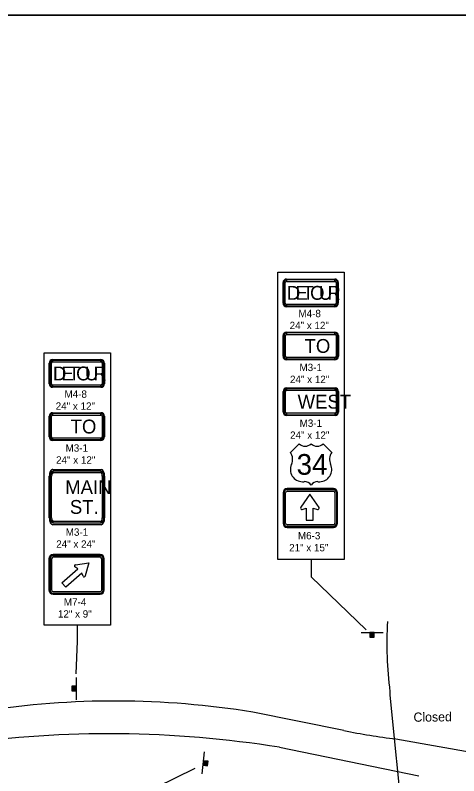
# Model space of a CAD drawing. Extents: x 10133 to 81668, y 6132 to 11018.
# Drawn here: x 11517 to 11999, y 9117 to 9944 of the extents above; entities that cross this region are included whole.
import ezdxf

# ---------------------------------------------------------------- set-up
doc = ezdxf.new("R2010")
doc.units = 0
for name, color, linetype in [('dsnTextFinalPlan', 7, 'Continuous'), ('Level 10', 7, 'Continuous'), ('Level 2', 7, 'Continuous'), ('Level 4', 7, 'Continuous'), ('Level 5', 7, 'Continuous'), ('SheetBorder', 7, 'Continuous'), ('SheetText', 7, 'Continuous')]:
    doc.layers.add(name, color=color, linetype=linetype)

msp = doc.modelspace()

# ---------------------------------------------------------------- linework, layer by layer
at = {"layer": 'dsnTextFinalPlan'}
for p, q in [((11554, 9353.14), (11554, 9319.35)), ((11609.55, 9357.72), (11558.58, 9357.72)), ((11614.13, 9319.35), (11614.13, 9353.14)), ((11558.58, 9314.77), (11609.55, 9314.77)), ((11893.21, 9273.15), (11917.21, 9273.15)), ((11907.57, 9272.79), (11902.69, 9272.79)), ((11902.69, 9272.54), (11907.57, 9272.54)), ((11907.57, 9272.31), (11902.69, 9272.31)), ((11902.69, 9272.08), (11907.57, 9272.08)), ((11907.57, 9271.89), (11902.69, 9271.89)), ((11902.69, 9271.71), (11907.57, 9271.71)), ((11907.57, 9271.41), (11902.69, 9271.41)), ((11902.69, 9271.18), (11907.57, 9271.18)), ((11907.57, 9270.99), (11902.69, 9271)), ((11902.69, 9270.71), (11907.57, 9270.71)), ((11907.57, 9270.38), (11902.69, 9270.38)), ((11902.69, 9270), (11907.57, 9270)), ((11907.57, 9269.81), (11902.69, 9269.82)), ((11902.69, 9269.45), (11907.57, 9269.43)), ((11907.57, 9269.25), (11902.69, 9269.25)), ((11902.69, 9268.97), (11907.57, 9268.97)), ((11907.57, 9268.78), (11902.69, 9268.78)), ((11902.69, 9268.5), (11907.57, 9268.5)), ((11583.66, 9224.07), (11583.66, 9200.07)), ((11579.01, 9214.59), (11579.01, 9209.71)), ((11579.29, 9209.71), (11579.29, 9214.59)), ((11579.49, 9214.59), (11579.49, 9209.71)), ((11579.77, 9209.71), (11579.77, 9214.59)), ((11579.96, 9214.59), (11579.95, 9209.71)), ((11580.32, 9209.71), (11580.34, 9214.59)), ((11580.52, 9214.59), (11580.52, 9209.71)), ((11580.89, 9209.71), (11580.89, 9214.59)), ((11581.22, 9214.59), (11581.22, 9209.71)), ((11581.5, 9209.71), (11581.52, 9214.59)), ((11581.7, 9214.59), (11581.7, 9209.71)), ((11581.93, 9209.71), (11581.93, 9214.59)), ((11582.22, 9214.59), (11582.22, 9209.71)), ((11582.4, 9209.71), (11582.4, 9214.59)), ((11582.6, 9214.59), (11582.6, 9209.71)), ((11582.83, 9209.71), (11582.83, 9214.59)), ((11583.05, 9214.59), (11583.05, 9209.71)), ((11583.3, 9209.71), (11583.3, 9214.59)), ((11874.53, 9166.61), (11775.63, 9186.42)), ((11931.03, 9157.44), (12148.4, 9119.44)), ((11720.39, 9119.35), (11723.1, 9143.2)), ((11804.44, 9148.37), (11956.07, 9117.16)), ((11722.37, 9133.58), (11721.82, 9128.73)), ((11722.06, 9128.7), (11722.61, 9133.55)), ((11722.84, 9133.52), (11722.29, 9128.68)), ((11722.52, 9128.65), (11723.07, 9133.5)), ((11723.27, 9133.47), (11722.71, 9128.63)), ((11722.89, 9128.61), (11723.44, 9133.45)), ((11723.74, 9133.42), (11723.19, 9128.57)), ((11723.41, 9128.55), (11723.96, 9133.39)), ((11724.16, 9133.37), (11723.59, 9128.53)), ((11723.89, 9128.5), (11724.44, 9133.34)), ((11724.76, 9133.3), (11724.21, 9128.46)), ((11724.58, 9128.42), (11725.13, 9133.26)), ((11725.33, 9133.24), (11724.76, 9128.4)), ((11725.14, 9128.35), (11725.7, 9133.2)), ((11725.88, 9133.18), (11725.33, 9128.33)), ((11725.61, 9128.3), (11726.16, 9133.15)), ((11726.35, 9133.12), (11725.8, 9128.28)), ((11726.08, 9128.25), (11726.63, 9133.09))]:
    msp.add_line(p, q, dxfattribs=at)
for points in [[(11802.9, 9664.76), (11874.97, 9664.76), (11874.97, 9352.54), (11802.9, 9352.54)], [(11802.9, 9664.76), (11874.97, 9664.76), (11874.97, 9352.54), (11802.9, 9352.54)], [(11548.64, 9577.16), (11620.7, 9577.16), (11620.7, 9281.07), (11548.64, 9281.07)], [(11548.64, 9577.16), (11620.7, 9577.16), (11620.7, 9281.07), (11548.64, 9281.07)], [(11907.57, 9273.06), (11902.66, 9273.06), (11902.66, 9268.15), (11907.57, 9268.15)], [(11583.58, 9209.71), (11583.58, 9214.62), (11578.67, 9214.62), (11578.67, 9209.71)], [(11722.09, 9133.61), (11721.54, 9128.73), (11726.42, 9128.17), (11726.97, 9133.05)]]:
    msp.add_lwpolyline(points, close=True, dxfattribs=at)
for points in [[(11838.93, 9352.54), (11838.93, 9333.57), (11898.89, 9275.89)], [(11591.14, 9334.16), (11589.52, 9337.67), (11572.19, 9322.38), (11568.03, 9327.09), (11585.36, 9342.38), (11582.06, 9344.41)], [(11582.85, 9346.58), (11597.21, 9348.65), (11593.35, 9334.67)], [(11584.67, 9281.07), (11584.67, 9263.58), (11583.34, 9228.28)], [(11924.53, 9208.75), (11924.53, 9205.04), (11938.44, 9064.44), (11960.57, 8858.09), (11970.22, 8724.25)], [(11587.6, 9045.25), (11587.6, 9064.06), (11712.82, 9125.45)]]:
    msp.add_lwpolyline(points, dxfattribs=at)
for centre, radius, start, end in [((11558.58, 9353.14), 4.58, 90, 180), ((11609.55, 9353.14), 4.58, 360, 90), ((11582.69, 9345.39), 1.16, 98.0346, 237.39274), ((11566.32, 9461.36), 115.96, 278.0346, 278.19506), ((11592.17, 9334.65), 1.14, 205.45459, 344.73406), ((11705.14, 9303.81), 115.96, 164.56669, 164.73406), ((11558.58, 9319.35), 4.58, 180, 270), ((11609.55, 9319.35), 4.58, 270, 0), ((12350.91, 9261.93), 429.68, 176.925, 187.10976), ((11625.49, 8265.99), 932.6, 80.73564, 98.86822), ((11618.87, 7976.32), 1186.65, 81.00318, 97.8988), ((12002.83, 9778.7), 625.39, 258.1619, 263.40729)]:
    msp.add_arc(centre, radius, start, end, dxfattribs=at)
at = {"layer": 'Level 10'}
for p, q in [((11812.11, 9657.25), (11864.72, 9657.25)), ((11812.11, 9654.75), (11812.11, 9656.31)), ((11864.72, 9656.31), (11864.72, 9654.75)), ((11808.35, 9630.95), (11808.35, 9653.49)), ((11809.29, 9653.49), (11810.85, 9653.49)), ((11865.97, 9653.49), (11867.54, 9653.49)), ((11868.48, 9653.49), (11868.48, 9630.95)), ((11810.85, 9630.95), (11809.29, 9630.95)), ((11867.54, 9630.95), (11865.97, 9630.95)), ((11812.11, 9628.13), (11812.11, 9629.69)), ((11864.72, 9627.19), (11812.11, 9627.19)), ((11864.72, 9629.69), (11864.72, 9628.13)), ((11812.15, 9599.57), (11864.77, 9599.57)), ((11812.15, 9597.06), (11812.15, 9598.63)), ((11864.77, 9598.63), (11864.77, 9597.06)), ((11808.4, 9573.26), (11808.4, 9595.81)), ((11809.34, 9595.81), (11810.9, 9595.81)), ((11866.02, 9595.81), (11867.58, 9595.81)), ((11868.52, 9595.81), (11868.52, 9573.26)), ((11810.9, 9573.26), (11809.34, 9573.26)), ((11867.58, 9573.26), (11866.02, 9573.26)), ((11554.09, 9543.35), (11554.09, 9565.89)), ((11555.02, 9565.89), (11556.59, 9565.89)), ((11557.84, 9569.65), (11610.46, 9569.65)), ((11557.84, 9567.15), (11557.84, 9568.71)), ((11610.46, 9568.71), (11610.46, 9567.15)), ((11611.71, 9565.89), (11613.27, 9565.89)), ((11614.21, 9565.89), (11614.21, 9543.35)), ((11812.15, 9570.44), (11812.15, 9572.01)), ((11864.77, 9569.5), (11812.15, 9569.5)), ((11864.77, 9572.01), (11864.77, 9570.44)), ((11556.59, 9543.35), (11555.02, 9543.35)), ((11557.84, 9540.53), (11557.84, 9542.09)), ((11610.46, 9542.09), (11610.46, 9540.53)), ((11613.27, 9543.35), (11611.71, 9543.35)), ((11610.46, 9539.59), (11557.84, 9539.59)), ((11808.51, 9512.64), (11808.51, 9535.19)), ((11809.45, 9535.19), (11811.02, 9535.19)), ((11812.27, 9538.95), (11864.88, 9538.95)), ((11812.27, 9536.44), (11812.27, 9538.01)), ((11864.88, 9538.01), (11864.88, 9536.44)), ((11866.14, 9535.19), (11867.7, 9535.19)), ((11868.64, 9535.19), (11868.64, 9512.64)), ((11554.13, 9485.66), (11554.13, 9508.21)), ((11555.07, 9508.21), (11556.64, 9508.21)), ((11557.89, 9511.97), (11610.5, 9511.97)), ((11557.89, 9509.46), (11557.89, 9511.03)), ((11610.5, 9511.03), (11610.5, 9509.46)), ((11611.75, 9508.21), (11613.32, 9508.21)), ((11614.26, 9508.21), (11614.26, 9485.66)), ((11811.02, 9512.64), (11809.45, 9512.64)), ((11812.27, 9509.82), (11812.27, 9511.39)), ((11864.88, 9508.88), (11812.27, 9508.88)), ((11864.88, 9511.39), (11864.88, 9509.82)), ((11867.7, 9512.64), (11866.14, 9512.64)), ((11556.64, 9485.66), (11555.07, 9485.66)), ((11557.89, 9482.84), (11557.89, 9484.41)), ((11610.5, 9484.41), (11610.5, 9482.84)), ((11613.32, 9485.66), (11611.75, 9485.66)), ((11610.5, 9481.9), (11557.89, 9481.9)), ((11558.08, 9450.38), (11610.69, 9450.38)), ((11554.32, 9397.77), (11554.32, 9442.87)), ((11555.26, 9442.87), (11556.83, 9442.87)), ((11558.08, 9445.37), (11558.08, 9448.5)), ((11610.69, 9448.5), (11610.69, 9446.94)), ((11611.95, 9442.87), (11613.51, 9442.87)), ((11614.45, 9442.87), (11614.45, 9397.77)), ((11808.39, 9425.04), (11808.39, 9391.78)), ((11809.52, 9391.78), (11809.52, 9425.04)), ((11811.22, 9391.78), (11811.22, 9425.04)), ((11863.06, 9429.55), (11812.89, 9429.55)), ((11812.91, 9428.42), (11863.08, 9428.42)), ((11812.91, 9426.73), (11863.08, 9426.73)), ((11864.77, 9425.04), (11864.77, 9391.78)), ((11866.46, 9425.04), (11866.46, 9391.78)), ((11867.57, 9391.78), (11867.57, 9425.04)), ((11837.47, 9423.46), (11827.55, 9409.2)), ((11847.56, 9409.02), (11837.47, 9423.46)), ((11829.29, 9406.93), (11833.64, 9408.33)), ((11833.64, 9408.33), (11833.64, 9395.28)), ((11841.3, 9408.15), (11841.3, 9408.33)), ((11841.3, 9408.33), (11845.82, 9406.93)), ((11841.3, 9395.1), (11841.3, 9408.15)), ((11556.83, 9397.77), (11555.26, 9397.77)), ((11558.08, 9392.13), (11558.08, 9395.27)), ((11610.69, 9393.7), (11610.69, 9392.13)), ((11613.51, 9397.77), (11611.95, 9397.77)), ((11833.64, 9395.28), (11833.64, 9395.1)), ((11833.64, 9395.1), (11841.3, 9395.1)), ((11610.69, 9390.25), (11558.08, 9390.25)), ((11812.89, 9387.27), (11863.06, 9387.27)), ((11863.08, 9390.09), (11812.91, 9390.09)), ((11863.08, 9388.4), (11812.91, 9388.4)), ((11555.15, 9353.14), (11555.15, 9319.35)), ((11556.87, 9353.14), (11556.87, 9319.35)), ((11609.55, 9356.57), (11558.58, 9356.57)), ((11609.55, 9354.86), (11558.58, 9354.86)), ((11611.27, 9319.35), (11611.27, 9353.14)), ((11612.99, 9319.35), (11612.99, 9353.14)), ((11558.58, 9317.63), (11609.55, 9317.63)), ((11558.58, 9315.92), (11609.55, 9315.92))]:
    msp.add_line(p, q, dxfattribs=at)
for points in [[(11864.72, 9656.31), (11812.11, 9656.31), (11812.11, 9654.75), (11864.72, 9654.75), (11864.72, 9656.31)], [(11809.29, 9653.49), (11809.29, 9630.95), (11810.85, 9630.95), (11810.85, 9653.49), (11809.29, 9653.49)], [(11867.54, 9630.95), (11867.54, 9653.49), (11865.97, 9653.49), (11865.97, 9630.95), (11867.54, 9630.95)], [(11812.11, 9628.13), (11864.72, 9628.13), (11864.72, 9629.69), (11812.11, 9629.69), (11812.11, 9628.13)], [(11864.77, 9598.63), (11812.15, 9598.63), (11812.15, 9597.06), (11864.77, 9597.06), (11864.77, 9598.63)], [(11809.34, 9595.81), (11809.34, 9573.26), (11810.9, 9573.26), (11810.9, 9595.81), (11809.34, 9595.81)], [(11867.58, 9573.26), (11867.58, 9595.81), (11866.02, 9595.81), (11866.02, 9573.26), (11867.58, 9573.26)], [(11555.02, 9565.89), (11555.02, 9543.35), (11556.59, 9543.35), (11556.59, 9565.89), (11555.02, 9565.89)], [(11610.46, 9568.71), (11557.84, 9568.71), (11557.84, 9567.15), (11610.46, 9567.15), (11610.46, 9568.71)], [(11613.27, 9543.35), (11613.27, 9565.89), (11611.71, 9565.89), (11611.71, 9543.35), (11613.27, 9543.35)], [(11812.15, 9570.44), (11864.77, 9570.44), (11864.77, 9572.01), (11812.15, 9572.01), (11812.15, 9570.44)], [(11557.84, 9540.53), (11610.46, 9540.53), (11610.46, 9542.09), (11557.84, 9542.09), (11557.84, 9540.53)], [(11809.45, 9535.19), (11809.45, 9512.64), (11811.02, 9512.64), (11811.02, 9535.19), (11809.45, 9535.19)], [(11864.88, 9538.01), (11812.27, 9538.01), (11812.27, 9536.44), (11864.88, 9536.44), (11864.88, 9538.01)], [(11867.7, 9512.64), (11867.7, 9535.19), (11866.14, 9535.19), (11866.14, 9512.64), (11867.7, 9512.64)], [(11555.07, 9508.21), (11555.07, 9485.66), (11556.64, 9485.66), (11556.64, 9508.21), (11555.07, 9508.21)], [(11610.5, 9511.03), (11557.89, 9511.03), (11557.89, 9509.46), (11610.5, 9509.46), (11610.5, 9511.03)], [(11613.32, 9485.66), (11613.32, 9508.21), (11611.75, 9508.21), (11611.75, 9485.66), (11613.32, 9485.66)], [(11812.27, 9509.82), (11864.88, 9509.82), (11864.88, 9511.39), (11812.27, 9511.39), (11812.27, 9509.82)], [(11557.89, 9482.84), (11610.5, 9482.84), (11610.5, 9484.41), (11557.89, 9484.41), (11557.89, 9482.84)], [(11555.26, 9442.87), (11555.26, 9397.77), (11556.83, 9397.77), (11556.83, 9442.87), (11555.26, 9442.87)], [(11610.69, 9448.5), (11558.08, 9448.5), (11558.08, 9446.94), (11610.69, 9446.94), (11610.69, 9448.5)], [(11613.51, 9397.77), (11613.51, 9442.87), (11611.95, 9442.87), (11611.95, 9397.77), (11613.51, 9397.77)], [(11558.08, 9392.13), (11610.69, 9392.13), (11610.69, 9393.7), (11558.08, 9393.7), (11558.08, 9392.13)]]:
    msp.add_lwpolyline(points, close=True, dxfattribs=at)
for centre, radius, start, end in [((11812.11, 9653.49), 3.76, 90, 180), ((11812.11, 9653.49), 2.82, 90.00021, 179.99985), ((11864.72, 9653.49), 3.76, 0, 90), ((11864.72, 9653.49), 2.82, 0, 90.00021), ((11812.11, 9653.49), 1.25, 90.00021, 179.99985), ((11864.72, 9653.49), 1.25, 0, 90.00021), ((11812.11, 9630.95), 3.76, 180, 270), ((11812.11, 9630.95), 2.82, 179.99985, 270.00006), ((11812.11, 9630.95), 1.25, 179.99985, 270.00006), ((11864.72, 9630.95), 2.82, 270.00006, 0.00027), ((11864.72, 9630.95), 1.25, 270.00006, 0.00027), ((11864.72, 9630.95), 3.76, 270, 359.99112), ((11812.15, 9595.81), 3.76, 90, 180), ((11812.15, 9595.81), 2.82, 90.00021, 179.99985), ((11864.77, 9595.81), 3.76, 0, 90), ((11864.77, 9595.81), 2.82, 0, 90.00021), ((11812.15, 9595.81), 1.25, 90.00021, 179.99985), ((11864.77, 9595.81), 1.25, 0, 90.00021), ((11812.15, 9573.26), 3.76, 180, 270), ((11812.15, 9573.26), 2.82, 179.99985, 270.00006), ((11812.15, 9573.26), 1.25, 179.99985, 270.00006), ((11864.77, 9573.26), 2.82, 270.00006, 0.00027), ((11864.77, 9573.26), 1.25, 270.00006, 0.00027), ((11864.77, 9573.26), 3.76, 270, 359.99112), ((11557.84, 9565.89), 3.76, 90, 180), ((11557.84, 9565.89), 2.82, 90.00021, 179.99985), ((11557.84, 9565.89), 1.25, 90.00021, 179.99985), ((11610.46, 9565.89), 3.76, 0, 90), ((11610.46, 9565.89), 2.82, 0, 90.00021), ((11610.46, 9565.89), 1.25, 0, 90.00021), ((11557.84, 9543.35), 3.76, 180, 270), ((11557.84, 9543.35), 2.82, 179.99985, 270.00006), ((11557.84, 9543.35), 1.25, 179.99985, 270.00006), ((11610.46, 9543.35), 2.82, 270.00006, 0.00027), ((11610.46, 9543.35), 1.25, 270.00006, 0.00027), ((11610.46, 9543.35), 3.76, 270, 359.99112), ((11812.27, 9535.19), 3.76, 90, 180), ((11812.27, 9535.19), 2.82, 90.00021, 179.99985), ((11812.27, 9535.19), 1.25, 90.00021, 179.99985), ((11864.88, 9535.19), 3.76, 0, 90), ((11864.88, 9535.19), 2.82, 0, 90.00021), ((11864.88, 9535.19), 1.25, 0, 90.00021), ((11557.89, 9508.21), 3.76, 90, 180), ((11557.89, 9508.21), 2.82, 90.00021, 179.99985), ((11557.89, 9508.21), 1.25, 90.00021, 179.99985), ((11610.5, 9508.21), 3.76, 0, 90), ((11610.5, 9508.21), 2.82, 0, 90.00021), ((11610.5, 9508.21), 1.25, 0, 90.00021), ((11812.27, 9512.64), 3.76, 180, 270), ((11812.27, 9512.64), 2.82, 179.99985, 270.00006), ((11812.27, 9512.64), 1.25, 179.99985, 270.00006), ((11864.88, 9512.64), 2.82, 270.00006, 0.00027), ((11864.88, 9512.64), 1.25, 270.00006, 0.00027), ((11864.88, 9512.64), 3.76, 270, 359.99112), ((11557.89, 9485.66), 3.76, 180, 270), ((11557.89, 9485.66), 2.82, 179.99985, 270.00006), ((11557.89, 9485.66), 1.25, 179.99985, 270.00006), ((11610.5, 9485.66), 2.82, 270.00006, 0.00027), ((11610.5, 9485.66), 1.25, 270.00006, 0.00027), ((11610.5, 9485.66), 3.76, 270, 359.99112), ((11812.89, 9425.04), 4.51, 90, 180), ((11812.91, 9425.04), 3.38, 90, 180), ((11812.91, 9425.04), 1.69, 90, 180), ((11863.06, 9425.04), 4.51, 360, 90), ((11863.08, 9425.04), 3.38, 0, 90), ((11863.08, 9425.04), 1.69, 0, 90), ((11828.76, 9408.33), 1.49, 144.26784, 290.86935), ((11846.21, 9408.38), 1.5, 254.96957, 25.41929), ((11812.89, 9391.78), 4.51, 180, 270), ((11812.91, 9391.78), 3.38, 180, 270), ((11812.91, 9391.78), 1.69, 180, 270), ((11863.06, 9391.78), 4.51, 270, 0), ((11863.08, 9391.78), 3.38, 270, 0), ((11863.08, 9391.78), 1.69, 270, 0), ((11558.58, 9353.14), 3.44, 90, 180), ((11558.58, 9353.14), 1.72, 90, 180), ((11609.55, 9353.14), 3.44, 0, 90), ((11609.55, 9353.14), 1.72, 0, 90), ((11558.58, 9319.35), 3.44, 180, 270), ((11558.58, 9319.35), 1.72, 180, 270), ((11609.55, 9319.35), 3.44, 270, 360), ((11609.55, 9319.35), 1.72, 270, 0)]:
    msp.add_arc(centre, radius, start, end, dxfattribs=at)
for centre, major_axis, ratio, start_param, end_param in [((11558.08, 9442.87), (0, 7.52), 0.5, 6.283185, 7.853982), ((11610.69, 9442.87), (0, 7.52), 0.5, 4.712389, 6.283185), ((11558.08, 9442.87), (0, 5.64), 0.5, 0.000004, 1.570794), ((11558.08, 9442.87), (0, 4.07), 0.307692, 0.000004, 1.570794), ((11610.69, 9442.87), (0, 5.64), 0.5, 4.712389, 6.283189), ((11610.69, 9442.87), (0, 4.07), 0.307692, 4.712389, 6.283189), ((11558.08, 9397.77), (0, 7.52), 0.5, 1.570796, 3.141593), ((11558.08, 9397.77), (0, 5.64), 0.5, 1.570794, 3.141594), ((11558.08, 9397.77), (0, 4.07), 0.307692, 1.570794, 3.141594), ((11610.69, 9397.77), (0, 5.64), 0.5, 3.141594, 4.712394), ((11610.69, 9397.77), (0, 4.07), 0.307692, 3.141594, 4.712394), ((11610.69, 9397.77), (0, 7.52), 0.5, 3.141593, 4.712234)]:
    msp.add_ellipse(centre, major_axis=major_axis, ratio=ratio, start_param=start_param, end_param=end_param, dxfattribs=at)
at = {"layer": 'Level 4'}
for p, q in [((11825.75, 9478.27), (11816.38, 9468.9)), ((11825.75, 9478.27), (11816.38, 9468.9)), ((11861.38, 9468.9), (11852, 9478.27)), ((11861.38, 9468.9), (11852, 9478.27)), ((11829.5, 9437.02), (11831.38, 9437.02)), ((11829.5, 9437.02), (11831.38, 9437.02)), ((11846.38, 9437.02), (11848.25, 9437.02)), ((11846.38, 9437.02), (11848.25, 9437.02))]:
    msp.add_line(p, q, dxfattribs=at)
for centre, radius, start, end in [((11832.31, 9484.97), 9.38, 225.57291, 314.42721), ((11832.31, 9484.97), 9.38, 225.57291, 314.42721), ((11845.44, 9484.97), 9.38, 225.57291, 314.42721), ((11845.44, 9484.97), 9.38, 225.57291, 314.42721), ((11805.71, 9461.25), 13.13, 334.98952, 35.66288), ((11805.71, 9461.25), 13.13, 334.98952, 35.66288), ((11872.04, 9461.25), 13.13, 144.33724, 205.01003), ((11872.04, 9461.25), 13.13, 144.33724, 205.01003), ((11829.5, 9450.15), 13.13, 154.98967, 270.00006), ((11829.5, 9450.15), 13.13, 154.98967, 270.00006), ((11848.25, 9450.15), 13.13, 270.00006, 25.01045), ((11848.25, 9450.15), 13.13, 270.00006, 25.01045), ((11831.38, 9427.65), 9.38, 36.86989, 90.00021), ((11831.38, 9427.65), 9.38, 36.86989, 90.00021), ((11846.38, 9427.65), 9.38, 90.00021, 143.13001), ((11846.38, 9427.65), 9.38, 90.00021, 143.13001)]:
    msp.add_arc(centre, radius, start, end, dxfattribs=at)
at = {"layer": 'SheetBorder'}
msp.add_lwpolyline([(10132.52, 9944.02), (13267.53, 9944.02), (13267.53, 7924.02), (10132.52, 7924.02)], close=True, dxfattribs=at)
at = {"layer": 'SheetText'}
msp.add_lwpolyline([(10132.52, 9944.02), (10132.52, 7924.02), (13267.53, 7924.02), (13267.53, 9944.02)], close=True, dxfattribs=at)

# ---------------------------------------------------------------- texts
at = {"layer": 'Level 10'}
for s, height, p in [('D', 15.03, (11812.59, 9634.7)), ('E', 15.03, (11821.83, 9634.7)), ('T', 15.03, (11829.61, 9634.7)), ('O', 15.03, (11837.82, 9634.7)), ('U', 15.03, (11847.41, 9634.7)), ('R', 15.03, (11856.65, 9634.7)), ('TO', 15.032, (11831.82, 9577.02)), ('D', 15.03, (11558.33, 9547.1)), ('E', 15.03, (11567.57, 9547.1)), ('T', 15.03, (11575.35, 9547.1)), ('O', 15.03, (11583.55, 9547.1)), ('U', 15.03, (11593.14, 9547.1)), ('R', 15.03, (11602.38, 9547.1)), ('WEST', 15.032, (11824.25, 9516.4)), ('TO', 15.032, (11577.55, 9489.42)), ('MAIN', 15.032, (11571.65, 9423.57)), ('ST.', 15.032, (11576.7, 9402.04))]:
    msp.add_text(s, height=height, dxfattribs=at).set_placement(p)
at = {"layer": 'Level 2'}
msp.add_text('Closed', height=10, rotation=0.74206, dxfattribs=at).set_placement((11950.26, 9176.02))
at = {"layer": 'Level 4'}
msp.add_text('34', height=22.5, dxfattribs=at).set_placement((11823.17, 9444.52))
msp.add_text('34', height=22.5, dxfattribs=at).set_placement((11823.17, 9444.52))
at = {"layer": 'Level 5'}
for s, p in [('M4-8', (11825.11, 9615.8)), ('24" x 12"', (11815.56, 9602.8)), ('M3-1', (11826.28, 9557.21)), ('24" x 12"', (11815.95, 9544.21)), ('M4-8', (11570.85, 9528.2)), ('24" x 12"', (11561.3, 9515.2)), ('M3-1', (11826.4, 9496.59)), ('24" x 12"', (11816.07, 9483.59)), ('M3-1', (11572.02, 9469.61)), ('24" x 12"', (11561.68, 9456.61)), ('M3-1', (11572.21, 9378.21)), ('M6-3', (11824.57, 9374.32)), ('24" x 24"', (11561.87, 9365.21)), ('21" x 15"', (11815.02, 9361.32)), ('M7-4', (11570.17, 9302.26)), ('12" x 9"', (11563.7, 9289.26))]:
    msp.add_text(s, height=8, dxfattribs=at).set_placement(p)

doc.saveas('drawing.dxf')
